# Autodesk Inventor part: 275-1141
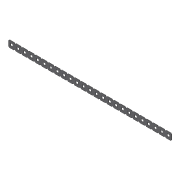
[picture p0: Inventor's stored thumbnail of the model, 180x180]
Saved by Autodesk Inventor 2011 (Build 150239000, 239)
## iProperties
Company: Autodesk Inc.
Created: 2005-08
Part Number: 275-1141
Document SubType Name: Sheet Metal
Designer: Autodesk Inc.
Density: 1 g/cm^3
Sheet Metal Rule: Default
Catalog Web Link: http://www.vexrobotics.com/products/accessories/structure/275-1141.html
Description: VEX bar with holes on 0.500" increments. Can be cut on 0.500" increments.
Vendor: Innovation First, Inc.
Author: Autodesk Inc.
Title: VEX Robotics Kit of Parts
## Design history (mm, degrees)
node "Face1"
  sketch "Sketch1"
    geometry: L1 (-15.07, 9.738)-(-23.96, 9.738); L2 (-25.865, 7.833)-(-25.865, -1.057); L3 (-23.96, -2.962)-(-15.07, -2.962); L4 (-13.165, -1.057)-(-13.165, 7.833); L5 (-25.865, 7.833)-(-23.96, 9.738); L6 (-25.865, -1.057)-(-23.96, -2.962); L7 (-15.07, -2.962)-(-13.165, -1.057); L8 (-13.165, 7.833)-(-15.07, 9.738); L9 (-21.801, 5.674)-(-17.229, 5.674); L10 (-17.229, 5.674)-(-17.229, 1.102); L11 (-17.229, 1.102)-(-21.801, 1.102); L12 (-21.801, 1.102)-(-21.801, 5.674); 4 further points
    constraints: 24 end point, 8 point on line, 4 parallel, 2 horizontal, 2 perpendicular
    dimensions: "d0" = 12.7 distance of point (-25.865, 9.738) point (-25.865, -2.962); "d1" = 12.7 distance of point (-13.165, 9.738) point (-25.865, 9.738); "d2" = 1.905 distance of L2.start point (-25.865, 9.738); "d3" = 1.905 distance of L1.end point (-25.865, 9.738) (= d2); "d4" = 1.905 distance of L2.end point (-25.865, -2.962) (= d2); "d5" = 1.905 distance of L3.start point (-25.865, -2.962) (= d4); "d6" = 1.905 distance of L3.end point (-13.165, -2.962) (= d2); "d7" = 1.905 distance of L4.start point (-13.165, -2.962) (= d6); "d8" = 1.905 distance of L4.end point (-13.165, 9.738) (= d2); "d9" = 1.905 distance of L1.start point (-13.165, 9.738) (= d8); "d10" = 4.572 distance of L11.end L9.start; "d11" = 4.572 distance of L10.end L11.end; "d12" = 4.064 distance between parallel lines of L1 L9; "d13" = 4.064 distance between parallel lines of L4 L10
body "Solid1"
pattern_linear "Rectangular Pattern1" dims "d17" = 12.7, "d23" = 12.7
face "Plate1" dims "Thickness" = 0.8509
other parameters: "BendRadius" = 0.8509 (= Thickness), "BendReliefWidth" = 0.8509 (= Thickness), "BendReliefDepth" = 0.42545 (= 0.5 x Thickness), "CornerReliefSize" = 3.4036 (= 4 x Thickness), "SeamGap" = 0.00508, "MinimumRemnant" = 1.7018 (= 2 x Thickness), "TransitionRadius" = 0.8509 (= BendRadius), "d14" = 0.8509 (= BendRadius), "JacobiRadiusSize" = 0.8509 (= Thickness), "GapSize" = 0.8509 (= Thickness)
